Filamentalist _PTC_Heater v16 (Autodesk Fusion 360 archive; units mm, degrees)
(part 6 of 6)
sketch "Sketch200" plane through (0, 139.2787, 0) normal (0, 1, 0) x axis (-1, 0, 0)
  line L1 (-85, -8.742) -> (-85, -111.6573)
  line L2 (-12.8286, 1.258) -> (-75, 1.258)
  line L3 (-0.8286, 63.7538) -> (-0.8286, 13.258)
  line L4 (28.4432, 73.7538) -> (9.1714, 73.7538)
  line L5 (38.4432, -111.6573) -> (38.4432, 63.7538)
  line L6 (-70, -126.6573) -> (23.4432, -126.6573)
  line L7 (38.4432, -207.5) -> (38.4432, -145.6573)
  line L8 (-75, -217.5) -> (28.4432, -217.5)
  line L9 (-85, -145.6573) -> (-85, -207.5)
  line L10 (23.4432, -130.6573) -> (-70, -130.6573)
  line L11 (36.4625, -218.0201) -> (36.7873, -218.3449)
  line L12 (-14.8286, 73.7538) -> (-75, 73.7538)
  line L13 (-4.8286, 15.258) -> (-4.8286, 63.7538)
  line L14 (-75, 5.258) -> (-14.8286, 5.258)
  line L15 (-85, 63.7538) -> (-85, 15.258)
  line L16 (-89, -216.5) -> (-89, 72.7538)
  line L17 (37.4432, -221.5) -> (-84, -221.5)
  line L18 (42.4432, 72.7538) -> (42.4432, -216.5)
  line L19 (-84, 77.7538) -> (37.4432, 77.7538)
  arc A1 centre (-75, -8.742) radius 10 clockwise from (-85, -8.742) to (-75, 1.258)
  arc A2 centre (-12.8286, 13.258) radius 12 clockwise from (-0.8286, 13.258) to (-12.8286, 1.258)
  arc A3 centre (9.1714, 63.7538) radius 10 clockwise from (-0.8286, 63.7538) to (9.1714, 73.7538)
  arc A4 centre (28.4432, 63.7538) radius 10 clockwise from (28.4432, 73.7538) to (38.4432, 63.7538)
  arc A5 centre (23.4432, -111.6573) radius 15 clockwise from (38.4432, -111.6573) to (23.4432, -126.6573)
  arc A6 centre (-70, -111.6573) radius 15 clockwise from (-70, -126.6573) to (-85, -111.6573)
  circle C1 centre (-79.4929, -128.6573) radius 1.7
  circle C2 centre (32.9285, -128.7178) radius 1.7
  arc A7 centre (28.4432, -207.5) radius 10 clockwise from (38.4432, -207.5) to (28.4432, -217.5)
  arc A8 centre (-75, -207.5) radius 10 clockwise from (-75, -217.5) to (-85, -207.5)
  arc A9 centre (-70, -145.6573) radius 15 clockwise from (-85, -145.6573) to (-70, -130.6573)
  arc A10 centre (23.4432, -145.6573) radius 15 clockwise from (23.4432, -130.6573) to (38.4432, -145.6573)
  circle C3 centre (-84.5529, -217.2726) radius 1.7
  arc A11 centre (37.9893, -217.2726) radius 1.7 clockwise from (36.4625, -218.0201) to (36.7257, -218.4098)
  arc A12 centre (37.9894, -219.547) radius 1.7 clockwise from (36.7257, -218.4098) to (36.7873, -218.3449)
  circle C4 centre (37.9893, 73.3188) radius 1.7
  circle C5 centre (-84.5342, 73.3188) radius 1.67
  circle C6 centre (-84.5528, 3.258) radius 1.7
  arc A13 centre (-14.8286, 63.7538) radius 10 clockwise from (-14.8286, 73.7538) to (-4.8286, 63.7538)
  arc A14 centre (-14.8286, 15.258) radius 10 clockwise from (-4.8286, 15.258) to (-14.8286, 5.258)
  arc A15 centre (-75, 15.258) radius 10 clockwise from (-75, 5.258) to (-85, 15.258)
  arc A16 centre (-75, 63.7538) radius 10 clockwise from (-85, 63.7538) to (-75, 73.7538)
  arc A17 centre (-84, -216.5) radius 5 clockwise from (-84, -221.5) to (-89, -216.5)
  arc A18 centre (37.4432, -216.5) radius 5 clockwise from (42.4432, -216.5) to (37.4432, -221.5)
  arc A19 centre (37.4432, 72.7538) radius 5 clockwise from (37.4432, 77.7538) to (42.4432, 72.7538)
  arc A20 centre (-84, 72.7538) radius 5 clockwise from (-89, 72.7538) to (-84, 77.7538)
extrude "Extrude58" cut sketch "Sketch200" profile of C1 C2 against normal blind 10.04
sketch "Sketch201" plane through (0, 139.2787, 0) normal (0, 1, 0) x axis (-1, 0, 0)
  line L1 (-85, -8.742) -> (-85, -111.6573)
  line L2 (-12.8286, 1.258) -> (-75, 1.258)
  line L3 (-0.8286, 63.7538) -> (-0.8286, 13.258)
  line L4 (28.4432, 73.7538) -> (9.1714, 73.7538)
  line L5 (38.4432, -111.6573) -> (38.4432, 63.7538)
  line L6 (-70, -126.6573) -> (23.4432, -126.6573)
  line L7 (38.4432, -207.5) -> (38.4432, -145.6573)
  line L8 (-75, -217.5) -> (28.4432, -217.5)
  line L9 (-85, -145.6573) -> (-85, -207.5)
  line L10 (23.4432, -130.6573) -> (-70, -130.6573)
  line L11 (36.4625, -218.0201) -> (36.7873, -218.3449)
  line L12 (-14.8286, 73.7538) -> (-75, 73.7538)
  line L13 (-4.8286, 15.258) -> (-4.8286, 63.7538)
  line L14 (-75, 5.258) -> (-14.8286, 5.258)
  line L15 (-85, 63.7538) -> (-85, 15.258)
  line L16 (-89, -216.5) -> (-89, 72.7538)
  line L17 (37.4432, -221.5) -> (-84, -221.5)
  line L18 (42.4432, 72.7538) -> (42.4432, -216.5)
  line L19 (-84, 77.7538) -> (37.4432, 77.7538)
  arc A1 centre (-75, -8.742) radius 10 clockwise from (-85, -8.742) to (-75, 1.258)
  arc A2 centre (-12.8286, 13.258) radius 12 clockwise from (-0.8286, 13.258) to (-12.8286, 1.258)
  arc A3 centre (9.1714, 63.7538) radius 10 clockwise from (-0.8286, 63.7538) to (9.1714, 73.7538)
  arc A4 centre (28.4432, 63.7538) radius 10 clockwise from (28.4432, 73.7538) to (38.4432, 63.7538)
  arc A5 centre (23.4432, -111.6573) radius 15 clockwise from (38.4432, -111.6573) to (23.4432, -126.6573)
  arc A6 centre (-70, -111.6573) radius 15 clockwise from (-70, -126.6573) to (-85, -111.6573)
  circle C1 centre (-79.4929, -128.6573) radius 1.7
  circle C2 centre (32.9285, -128.7178) radius 1.7
  arc A7 centre (28.4432, -207.5) radius 10 clockwise from (38.4432, -207.5) to (28.4432, -217.5)
  arc A8 centre (-75, -207.5) radius 10 clockwise from (-75, -217.5) to (-85, -207.5)
  arc A9 centre (-70, -145.6573) radius 15 clockwise from (-85, -145.6573) to (-70, -130.6573)
  arc A10 centre (23.4432, -145.6573) radius 15 clockwise from (23.4432, -130.6573) to (38.4432, -145.6573)
  circle C3 centre (-84.5529, -217.2726) radius 1.7
  arc A11 centre (37.9893, -217.2726) radius 1.7 clockwise from (36.4625, -218.0201) to (36.7257, -218.4098)
  arc A12 centre (37.9894, -219.547) radius 1.7 clockwise from (36.7257, -218.4098) to (36.7873, -218.3449)
  circle C4 centre (37.9893, 73.3188) radius 1.7
  circle C5 centre (-84.5342, 73.3188) radius 1.67
  circle C6 centre (-84.5528, 3.258) radius 1.7
  arc A13 centre (-14.8286, 63.7538) radius 10 clockwise from (-14.8286, 73.7538) to (-4.8286, 63.7538)
  arc A14 centre (-14.8286, 15.258) radius 10 clockwise from (-4.8286, 15.258) to (-14.8286, 5.258)
  arc A15 centre (-75, 15.258) radius 10 clockwise from (-75, 5.258) to (-85, 15.258)
  arc A16 centre (-75, 63.7538) radius 10 clockwise from (-85, 63.7538) to (-75, 73.7538)
  arc A17 centre (-84, -216.5) radius 5 clockwise from (-84, -221.5) to (-89, -216.5)
  arc A18 centre (37.4432, -216.5) radius 5 clockwise from (42.4432, -216.5) to (37.4432, -221.5)
  arc A19 centre (37.4432, 72.7538) radius 5 clockwise from (37.4432, 77.7538) to (42.4432, 72.7538)
  arc A20 centre (-84, 72.7538) radius 5 clockwise from (-89, 72.7538) to (-84, 77.7538)
extrude "Extrude63" new body sketch "Sketch201" along normal blind 2.5 bodies "inside-cover"
move "Move32"
delete_face "DeleteFace10"
offset_faces "OffsetFaces9" distance 0.5
offset_faces "OffsetFaces2" distance -2
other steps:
extrude "Extrude1" cut sketch "Sketch153" profile of L1 L3 L5 L6 L7 L8 against normal blind 160
extrude "Extrude2" cut sketch "Sketch168" profile of L3 L9 L58 L59 L60 L61 L66 L67 L68 L69 against normal blind 150
extrude "Extrude5" cut sketch "Sketch184" profile of L2 L4 L6 L8 L9 L10 L11 L12 distance 270 bodies "Body"
extrude "Extrude7" cut sketch "Sketch129" against normal blind 10
extrude "Extrude8" cut sketch "Sketch130" against normal blind 10
extrude "Extrude9" cut sketch "Sketch131" against normal blind 10
extrude "Extrude10" cut sketch "Sketch132" against normal blind 10
extrude "Extrude11" cut sketch "Sketch133" against normal blind 10
extrude "Extrude12" cut sketch "Sketch134" against normal blind 10
extrude "Extrude13" cut sketch "Sketch135" against normal blind 10
extrude "Extrude14" cut sketch "Sketch136" against normal blind 10
extrude "Extrude15" cut sketch "Sketch137" against normal blind 10
extrude "Extrude16" cut sketch "Sketch138" against normal blind 10
extrude "Extrude17" cut sketch "Sketch139" against normal blind 10
extrude "Extrude18" cut sketch "Sketch140" against normal blind 10
extrude "Extrude19" cut sketch "Sketch141" against normal blind 10
extrude "Extrude20" cut sketch "Sketch142" against normal blind 10
extrude "Extrude21" cut sketch "Sketch143" against normal blind 10
extrude "Extrude22" cut sketch "Sketch144" against normal blind 10
extrude "Extrude23" cut sketch "Sketch145" against normal blind 10
extrude "Extrude24" cut sketch "Sketch146" against normal blind 10
extrude "Extrude25" cut sketch "Sketch147" against normal blind 10
extrude "Extrude26" cut sketch "Sketch148" against normal blind 10
extrude "Extrude27" cut sketch "Sketch149" against normal blind 10
extrude "Extrude28" cut sketch "Sketch150" against normal blind 30
extrude "Extrude29" cut sketch "Sketch151" against normal blind 14
extrude "Extrude37" cut sketch "Sketch167" against normal blind 1
extrude "Extrude56" cut sketch "Sketch196" against normal blind 10.04
base_feature "Base Feature1"
base_feature "Base Feature2"
base_feature "Base Feature3"
base_feature "Base Feature4"
base_feature "Base Feature5"
base_feature "Base Feature6"
base_feature "Base Feature7"
create_component "CreateComponent4"
create_component "CreateComponent5"
remove_body "RemoveBody172"
remove_body "RemoveBody173"
remove_body "RemoveBody174"
remove_body "RemoveBody175"
remove_body "RemoveBody176"
remove_body "RemoveBody183"
remove_body "RemoveBody184"
remove_body "RemoveBody185"
remove_body "RemoveBody186"
named bodies: "Body", "Body (1)", "Spacer", "inside-cover"

design "rocker switch 1"
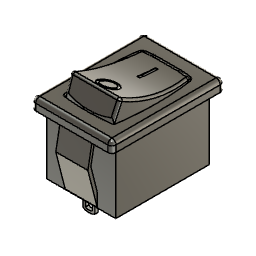
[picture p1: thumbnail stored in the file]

design "Rocker Switch - Arcolectric R13 112C AAA"
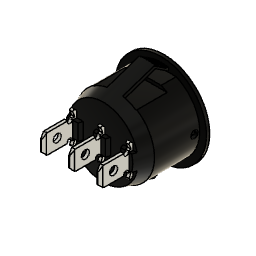
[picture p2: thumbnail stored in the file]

design "1W1209WK"
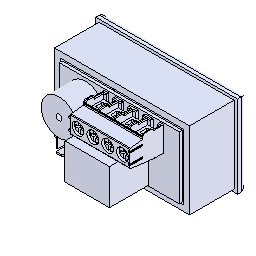
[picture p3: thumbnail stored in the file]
description: STEP AP214
part number: 1W1209WK
description: Part Number
part number: 12381BS-8.3
part number: 1Connector 4P_30mm
part number: 1XH2_54_2PIN
base_feature "Base Feature1"
base_feature "Base Feature1"
base_feature "Base Feature1"
base_feature "Base Feature1"
base_feature "Base Feature1"
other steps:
create_component "CreateComponent1"
create_component "CreateComponent2"
create_component "CreateComponent3"
create_component "CreateComponent4"
create_component "CreateComponent5"

design "Switch,rocker,SPST,black,Iluminated"
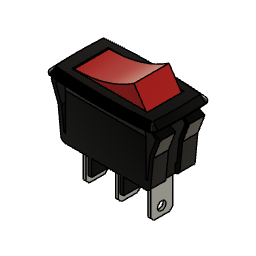
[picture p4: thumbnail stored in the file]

design "Mini Rocker Switch"
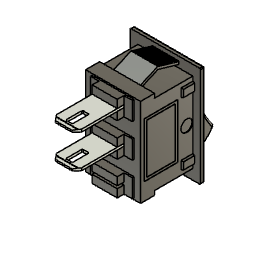
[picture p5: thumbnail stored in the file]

design "Anycubic_Photon_Heater_Lid_v2"
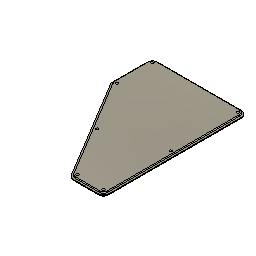
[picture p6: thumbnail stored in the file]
description: STEP AP203
part number: Anycubic Photon Heater Lid
base_feature "Base Feature"

design "heater element"
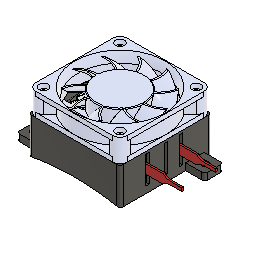
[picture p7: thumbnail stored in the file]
description: STEP AP214
part number: heater element
description: Part Number
part number: heater body
part number: 6015 FAN
base_feature "Base Feature1"
base_feature "Base Feature1"
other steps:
create_component "CreateComponent1"
create_component "CreateComponent2"

design "EL90005--STD--Power Supply 10A 12V (Bicolt Automática 120W)"
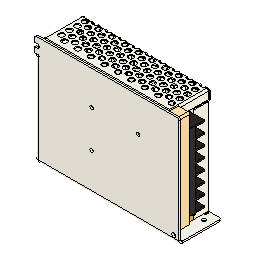
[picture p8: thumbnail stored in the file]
description: STEP AP214
part number: arrangementsContainer
base_feature "Base Feature"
